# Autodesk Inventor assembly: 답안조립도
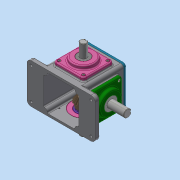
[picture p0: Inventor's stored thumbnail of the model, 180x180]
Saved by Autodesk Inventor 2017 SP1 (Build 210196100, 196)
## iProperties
Part Number: 답안조립도
Material: 일반
Document SubType Name: Assembly
Designer: MRC
Mass: 3235.88 g
Surface Area: 2651.66 cm^2
Volume: 866.536 cm^3
Density: 3.73427 g/cm^3
Author: MRC
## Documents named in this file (16)
- C:\Users\MRC\Desktop\620307V1008\답안조립도.iam
- C:\Users\MRC\Desktop\620307V1008\본체.ipt
- C:\Users\MRC\Desktop\620307V1008\개스킷.ipt
- C:\Users\MRC\Desktop\620307V1008\메인베벨기어.ipt
- C:\Users\MRC\Desktop\620307V1008\메인축.ipt
- C:\Users\MRC\Desktop\620307V1008\메인커버.ipt
- C:\Users\MRC\Desktop\620307V1008\베어링 6203.ipt
- C:\Users\MRC\Desktop\620307V1008\베어링 6204.ipt
- C:\Users\MRC\Desktop\620307V1008\볼트 M4.ipt
- C:\Users\MRC\Desktop\620307V1008\상부커버.ipt
- C:\Users\MRC\Desktop\620307V1008\서브베벨기어.ipt
- C:\Users\MRC\Desktop\620307V1008\서브축.ipt
- C:\Users\MRC\Desktop\620307V1008\서브커버.ipt
- C:\Users\MRC\Desktop\620307V1008\오일 실 17 32 8.ipt
- C:\Users\MRC\Desktop\620307V1008\오일 실 20 35 8.ipt
- C:\Users\MRC\Desktop\620307V1008\키 4x4.ipt
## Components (1 placed, 1 different names)
1. 개스킷:1
